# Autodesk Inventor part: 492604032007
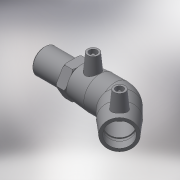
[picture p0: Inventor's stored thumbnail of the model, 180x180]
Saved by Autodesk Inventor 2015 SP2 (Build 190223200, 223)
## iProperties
Created: 2017-06
Part Number: 492604032007
Material: Generic
Description: PLASSON 45° ELBOW TRANSITION MALE 32-3/4"
Document SubType Name: Modeling
Designer: KIM
Mass: 106.583 g
Surface Area: 322.373 cm^2
Volume: 106.583 cm^3
Density: 1 g/cm^3
Appearance: Default
Author: KIM
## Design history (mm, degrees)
derived "492604.ipt"
feature "Solid1::492604.ipt"
tag "TaggingFeature1"
body "Solid1"
other parameters: "d2" = 44, "d4" = 23.5, "d5" = 39.6, "d8" = 168 deg, "d10" = 15.6, "d11" = 5.2, "d29" = 43, "d30" = 15, "d31" = 32.9, "d34" = 5 deg, "d41" = 4, "d42" = 14, "d43" = 0, "d49" = 32, "d50" = 20.8, "d51" = 15.6, "d52" = 40.17, "d54" = 135 deg, "d86" = 19.8, "d87" = 135 deg, "d88" = 94, "d90" = 39, "d91" = 0, "d92" = 39, "d93" = 0, "d101" = 3, "d102" = 0, "d107" = 0.1, "d108" = 23, "d109" = 26.441, "d110" = 29, "d111" = 7.25, "d112" = 44, "d113" = 18.5087, "d114" = 26.1, "d116" = 1.32, "d122" = 0, "d123" = 1.32205, "d_" = 32, "L_" = 123, "L_1" = 39, "D_" = 23, "A_" = 43, "d_2" = 12, "L_2" = 29, "R_" = 26.441, "D_1" = 44
